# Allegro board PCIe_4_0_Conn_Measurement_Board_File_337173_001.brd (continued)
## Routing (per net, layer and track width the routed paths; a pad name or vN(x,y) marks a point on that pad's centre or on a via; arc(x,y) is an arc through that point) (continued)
GND3: length 97.5
  TOP w0.259: R48.1 v1(73.66,13.82) ; R49.1 v1(74.93,13.82) ; R47.1 v1(71.12,12.55) ; R45.1 v1(59.69,13.69) ; R46.1 v1(70.1,12.55) ; R44.1 v1(55.25,13.94)
  TOP w0.508: v1(56.54,6.01) 56.44,6.01 56.05,5.62 P1.B13 ; P1.A18 61.05,5.61 61.44,6.01 v1(61.54,6.01) ; 65.39,6.01 63.72,6.01 ; 65.39,6.01 v1(65.54,6.01) ; 65.39,6.01 65.05,5.66 P1.B22 ; 63.72,6.01 v1(63.54,6.01) ; 63.72,6.01 64.05,5.68 P1.B21 ; v1(44.54,6.01) 44.45,6.01 44.05,5.6 P1.A3 ; v1(49.54,6.01) 49.64,6.01 50.05,5.6 P1.A9 ; 67.72,6.01 68.05,5.68 P1.B25 ; 67.72,6.01 v1(67.54,6.01) ; 67.72,6.01 69.34,6.01 ; v1(45.54,6.01) 45.44,6.01 45.05,5.61 P1.A4 ; P1.B16 59.05,5.6 58.64,6.01 v1(58.55,6.01) ; P1.A10 51.05,5.59 51.46,6.01 v1(51.55,6.01) ; P1.B29 72.05,5.59 71.63,6.01 v1(71.55,6.01) ; P1.A1 42.05,5.6 42.45,6.01 v1(42.55,6.01) ; P1.B26 69.05,5.71 69.34,6.01 ; v1(69.55,6.01) 69.34,6.01 ; v1(43.55,6.01) 43.45,6.01 43.05,5.61 P1.A2 ; v1(74.54,6.01) 74.63,6.01 75.05,5.59 P1.B32 ; v1(47.55,6.01) 47.64,6.01 48.05,5.6 P1.B7
  BOTTOM w0.259: R50.2 v1(61.34,13.69) ; R51.2 v1(69.22,12.04) ; v1(71.83,12.04) 71.75,11.96 R53.2 ; R54.2 v1(72.77,12.04) ; R52.2 v1(68.2,12.04) ; R55.2 v1(75.95,13.82)
  BOTTOM w0.508: P1.A1 42.05,5.63 42.43,6.01 v1(42.55,6.01) ; v1(61.54,6.01) 61.46,6.01 61.05,5.6 P1.A18 ; v1(69.55,6.01) 69.84,6.01 ; 69.84,6.01 71.26,6.01 ; 69.84,6.01 70.05,5.8 P1.A27 ; 71.26,6.01 71.05,5.79 P1.A28 ; 71.26,6.01 v1(71.55,6.01) ; P1.A24 67.05,5.8 67.26,6.01 ; v1(67.54,6.01) 67.26,6.01 ; 67.26,6.01 65.82,6.01 ; v1(49.54,6.01) 49.83,6.01 ; 49.83,6.01 50.05,5.79 P1.A9 ; 49.83,6.01 51.27,6.01 ; P1.A12 55.05,5.61 55.45,6.01 v1(55.55,6.01) ; v1(44.54,6.01) 44.43,6.01 44.05,5.63 P1.A3 ; 65.82,6.01 v1(65.54,6.01) ; 65.82,6.01 66.05,5.78 P1.A23 ; v1(58.55,6.01) 58.46,6.01 58.05,5.6 P1.A15 ; v1(51.55,6.01) 51.27,6.01 ; 51.27,6.01 51.05,5.78 P1.A10 ; P1.A31 74.05,5.59 74.46,6.01 v1(74.54,6.01) ; v1(63.54,6.01) 63.46,6.01 63.05,5.59 P1.A20 ; v1(43.55,6.01) 43.43,6.01 43.05,5.63 P1.A2 ; P1.A4 45.05,5.63 45.43,6.01 v1(45.54,6.01)
  vias: v2(23.81,15.1) v2(23.81,14.19) v2(24.27,15.31) v2(24.27,13.98) v2(24.73,15.1) v2(24.73,14.19) v2(32.67,32.55) v2(32.88,33.01) v2(32.88,32.1) v2(33.8,33.01) v2(33.8,32.1) v2(34,32.55) v2(43.53,41.69) v2(43.74,42.15) v2(43.74,41.23) v2(44.65,42.15) v2(44.65,41.23) v2(44.86,41.69) v2(54.99,43.95) v2(55.19,44.41) v2(55.19,43.5) v2(56.11,44.41) v2(56.11,43.5) v2(56.31,43.95) v2(63.31,31.59) v2(63.31,30.67) v2(63.77,31.79) v2(63.77,30.47) v2(64.22,31.59) v2(64.22,30.67) v2(74.76,46.19) v2(74.97,46.65) v2(74.97,45.74) v2(75.88,46.65) v2(75.88,45.74) v2(76.09,46.19) v2(83.36,36.34) v2(83.56,36.8) v2(83.56,35.88) v2(84.48,36.8) v2(84.48,35.88) v2(84.68,36.34) v2(93.23,22.84) v2(93.44,23.3) v2(93.44,22.38) v2(94.35,23.3) v2(94.35,22.38) v2(94.56,22.84) v2(95.11,32.48) v2(95.11,31.56) v2(95.57,32.68) v2(95.56,31.36) v2(96.03,32.48) v2(96.02,31.56) v2(103.48,15.11) v2(103.48,14.19) v2(103.93,15.31) v2(103.93,13.99) v2(104.39,15.11) v2(104.39,14.19)
CLKREQ-GF1: length 7.4
  TOP w0.198: P1.B12 54.95,3.73 54.95,10.2 arc(55.03,10.59) C35.1
CLKREQ-GF2: length 7.4
  TOP w0.198: P2.B12 308.95,3.73 308.95,10.2 arc(309.03,10.59) C29.1
FACE2FACE: length 16.5
  TOP w0.198: J112.1 J106.1
FACE2FACE_TH: length 16.5
  BOTTOM w0.198: 288.16,227.37 J118.1
LOAD: length 45.7
  TOP w0.198: R66.2 63.12,246.42 ; 63.12,246.42 R67.2 ; 63.12,246.42 J105.1
LOAD_TH_TH: length 45.7
  BOTTOM w0.198: R69.2 317.12,246.42 ; 317.12,246.42 R68.2 ; 317.12,246.42 J117.1
PRESENT1-GF1: length 7.7
  TOP w0.198: P1.B31 73.95,3.73 73.95,8.68 arc(74.21,9.95) C38.1
PRESENT1-GF2: length 7.7
  TOP w0.198: P2.B31 327.95,3.73 327.95,8.68 arc(328.21,9.95) C32.1
PRESENT-GF1: length 7.4
  TOP w0.198: P1.B17 60.05,10.05 arc(59.95,10.51) C36.1
PRESENT-GF2: length 7.4
  TOP w0.198: P2.B17 314.05,10.05 arc(313.95,10.51) C30.1
PRIMARY_THRU: length 91.5
  TOP w0.198: J111.1 71.81,265.47 arc(70.84,265.28) 70.03,264.73 69.54,264.24 arc(66.77,262.4) 63.51,261.75 60.88,261.75 arc(57.8,262.36) 55.19,264.1 54.7,264.59 arc(53.73,265.24) 52.57,265.47 51.46,265.47 arc(50.8,265.6) 50.25,265.97 49.16,267.06 arc(48.23,267.68) 47.15,267.89 43.37,267.89 arc(42.03,267.63) 40.9,266.87 40.62,266.59 arc(39.38,265.76) 37.91,265.47 J104.1
PRIMARY_THRU_TH: length 91.5
  BOTTOM w0.198: J123.1 325.81,265.47 arc(324.84,265.28) 324.03,264.73 323.54,264.24 arc(320.77,262.4) 317.51,261.75 314.88,261.75 arc(311.8,262.36) 309.19,264.1 308.7,264.59 arc(307.73,265.24) 306.57,265.47 305.46,265.47 arc(304.8,265.6) 304.25,265.97 303.16,267.06 arc(302.23,267.68) 301.15,267.89 297.37,267.89 arc(296.03,267.63) 294.9,266.87 294.62,266.59 arc(293.38,265.76) 291.91,265.47 J116.1
PWRBRK-GF1: length 7.6
  TOP w0.198: P1.B30 73.05,9.56 arc(73.21,10.36) C37.1
PWRBRK-GF2: length 7.6
  TOP w0.198: P2.B30 327.05,9.56 arc(327.21,10.36) C31.1
REFCLK-SMT_N: length 2.9
  TOP w0.198: J66.A13 69.05,359.14 69.07,359.16 R64.1
REFCLK-SMT_P: length 2.9
  TOP w0.198: J66.A14 69.06,358.14 69.07,358.14 R65.1
REFCLK-TH_N: length 5.1
  BOTTOM w0.198: J44.A13 318.77,359.33 arc(319.02,359.16) 319.31,359.11 arc(319.47,359.14) 319.6,359.23 arc(319.72,359.31) 319.86,359.33 323.5,359.33 arc(323.6,359.35) R62.1
REFCLK-TH_P: length 5.1
  BOTTOM w0.198: R63.1 arc(325.33,358.62) 324.93,358.7 321.58,358.7 arc(321.13,358.61) J44.A14
RSVD1-GF1: length 7.7
  BOTTOM w0.198: P1.A32 75.15,3.73 75.15,9.1 arc(75.35,10.15) C34.2
RSVD1-GF2: length 7.7
  BOTTOM w0.198: P2.A32 329.15,3.73 329.15,9.1 arc(329.35,10.15) C28.2
RSVD-GF1: length 7.5
  BOTTOM w0.198: P1.A19 62.15,3.74 62.15,6.54 arc(62.1,6.79) 61.97,7 61.9,7.06 arc(61.74,7.3) 61.68,7.58 61.68,10.07 arc(61.59,10.52) C33.2
RSVD-GF2: length 7.5
  BOTTOM w0.198: P2.A19 316.15,3.74 316.15,7.08 arc(316.06,7.54) 315.8,7.94 arc(315.65,8.16) 315.6,8.43 315.6,10.28 arc(315.53,10.62) C27.2
RX0-GF1_N: length 47
  BOTTOM w0.198: P1.A16 59.13,3.72 59.13,6.52 arc(59,7.2) 58.61,7.77 58.46,7.92 58.02,8.36 arc(57.86,8.54) 57.7,8.72 arc(57.56,8.89) 57.43,9.07 arc(56.8,10.02) 56.58,11.14 56.58,17.96 arc(55.96,21.07) 54.2,23.7 arc(53.02,24.49) 51.63,24.77 48.31,24.77 arc(45.4,25.97) 44.19,28.88 J100.1
RX0-GF1_P: length 47
  BOTTOM w0.198: P1.A17 60.05,8.43 arc(59.91,9.12) 59.52,9.71 59.5,9.72 arc(58.9,10.63) 58.69,11.7 58.69,13.55 arc(59.06,15.42) 60.11,17 60.15,17.04 61.87,18.76 arc(65.47,21.16) 69.71,22 71.98,22 arc(73.14,22.23) 74.12,22.89 arc(74.53,23.5) 74.68,24.23 74.68,26.41 arc(74.43,27.64) 73.74,28.68 72.1,30.31 arc(71.19,30.92) 70.13,31.13 J101.1
RX0-GF2_N: length 48.9
  BOTTOM w0.198: P2.A16 313.13,3.72 313.13,6.52 arc(313,7.2) 312.61,7.77 312.46,7.92 312.02,8.36 arc(311.86,8.54) 311.7,8.72 arc(311.56,8.89) 311.43,9.07 arc(310.8,10.02) 310.58,11.14 310.58,17.96 arc(309.96,21.07) 308.2,23.7 arc(307.02,24.49) 305.63,24.77 300.73,24.77 arc(299.47,25.02) 298.4,25.73 297.21,26.92 arc(296.6,28.38) 297.21,29.85 arc(297.94,30.94) 298.19,32.23 J82.1
RX0-GF2_P: length 49
  BOTTOM w0.198: J83.1 324.6,31.13 arc(326.94,30.66) 328.93,29.34 arc(329.27,28.83) 329.39,28.23 329.39,24.46 arc(329.22,23.64) 328.76,22.95 328.55,22.73 arc(327.74,22.19) 326.78,22 323.71,22 arc(319.47,21.16) 315.87,18.76 314.15,17.04 314.11,17 arc(313.06,15.42) 312.69,13.55 312.69,11.7 arc(312.9,10.63) 313.5,9.72 313.52,9.71 arc(313.91,9.12) 314.05,8.43 P2.A17
RX0-SMT_N: length 48
  TOP w0.198: J56.1 89.18,381.58 89.18,381.59 88.49,381.59 arc(86.64,381.96) 85.06,383.01 arc(81.46,384.5) 77.85,383.01 75.27,380.43 arc(73.82,378.25) 73.3,375.68 73.3,360.91 arc(72.9,358.86) 71.73,357.12 arc(70.64,356.39) 69.35,356.14 J66.A16
RX0-SMT_P: length 48
  TOP w0.198: J66.A17 72.22,355.14 arc(75.96,355.88) 79.13,358 arc(80.13,359.39) 80.61,361.04 arc(80.88,362.4) 81.65,363.56 87.11,369.01 arc(91.03,370.64) 94.94,369.01 96.68,367.28 arc(97.69,366.6) 98.88,366.37 J86.1
RX0-TH_N: length 47.6
  BOTTOM w0.198: J44.A16 320.11,356.35 arc(319.89,356.4) 319.7,356.53 arc(319.61,356.75) 319.7,356.97 319.77,357.05 arc(320.66,357.41) 321.54,357.05 arc(321.86,356.83) 322.24,356.76 325.69,356.76 arc(327.22,357.06) 328.51,357.92 arc(329.07,358.91) 329.26,360.03 329.26,374.98 arc(329.69,377.14) 330.91,378.97 arc(333.83,380.92) 337.26,381.6 345.14,381.6 J20.1
RX0-TH_P: length 47.6
  BOTTOM w0.198: J67.1 346.26,366.37 arc(343.5,365.82) 341.17,364.26 arc(339.71,362.07) 339.19,359.49 arc(338.91,358.05) 338.1,356.84 337.92,356.67 arc(336.32,355.6) 334.43,355.22 321.68,355.22 arc(321.51,355.25) 321.37,355.35 arc(321.25,355.43) 321.1,355.46 320.55,355.46 arc(320.23,355.52) 319.96,355.7 arc(319.53,355.88) 319.09,355.7 J44.A17
RX1-GF1_N: length 47
  BOTTOM w0.198: P1.A21 64.13,3.72 64.13,6.44 arc(64.06,6.8) 63.86,7.11 arc(63.53,7.6) 63.41,8.19 63.41,11.45 arc(63.82,13.49) 64.97,15.21 65.09,15.33 arc(67.18,16.73) 69.65,17.22 75.8,17.22 arc(78.42,17.74) 80.64,19.23 arc(81.9,21.11) 82.35,23.34 82.35,27.37 82.35,27.86 arc(82.59,29.07) 83.28,30.1 arc(83.83,30.93) 84.02,31.9 J102.1
RX1-GF1_P: length 47
  BOTTOM w0.198: J103.1 93.89,17.9 arc(93.4,15.39) 91.97,13.26 arc(89.98,11.92) 87.62,11.46 85.6,11.46 85.6,11.45 arc(82.81,12.01) 80.44,13.59 arc(78.94,14.59) 77.17,14.94 71.41,14.94 arc(69.33,14.53) 67.57,13.35 66.07,11.85 arc(65.24,10.46) 64.95,8.87 64.95,3.73 P1.A22
RX1-GF2_N: length 49
  BOTTOM w0.198: J84.1 338.02,30.32 arc(337.88,29.62) 337.49,29.03 336.85,28.39 arc(336.15,27.93) 335.33,27.76 arc(334.04,27.23) 333.5,25.93 333.5,23.51 arc(333.77,22.18) 334.52,21.06 arc(334.88,20.18) 334.52,19.3 333.56,18.35 arc(331.77,17.51) 329.8,17.22 323.65,17.22 arc(321.18,16.73) 319.09,15.33 318.97,15.21 arc(317.82,13.49) 317.41,11.45 317.41,8.19 arc(317.53,7.6) 317.86,7.11 arc(318.06,6.8) 318.14,6.44 318.14,3.72 P2.A21
RX1-GF2_P: length 49
  BOTTOM w0.198: P2.A22 318.95,3.73 318.95,8.87 arc(319.24,10.46) 320.07,11.85 321.04,12.82 321.57,13.35 arc(323.33,14.53) 325.41,14.94 331.91,14.94 arc(333.1,15.18) 334.11,15.86 arc(334.18,15.92) 334.24,15.98 334.29,16.03 arc(335.57,16.56) 336.85,16.03 340.18,12.7 arc(341.47,11.84) 343,11.54 arc(344.95,11.92) 346.61,13.03 arc(347.56,14.45) 347.89,16.13 J85.1
RX1-SMT_N: length 48
  TOP w0.198: J87.1 96.64,346.42 arc(94.84,345.67) 94.1,343.88 94.1,343.43 arc(93.83,342.11) 93.08,340.99 92.86,340.77 arc(92.61,340.6) 92.31,340.54 86.12,340.54 arc(85.03,340.76) 84.1,341.38 arc(83.61,342.11) 83.44,342.98 83.44,344.7 arc(83.11,346.33) 82.19,347.71 77.9,352.01 arc(74.86,353.26) 71.83,352.01 71.5,351.67 arc(70.9,351.28) 70.21,351.14 J66.A21
RX1-SMT_P: length 48
  TOP w0.198: J88.1 80.18,327.72 arc(79.03,327.95) 78.05,328.6 arc(77.58,329.3) 77.42,330.13 77.42,331.11 arc(77.55,331.77) 77.93,332.33 arc(78.73,333.53) 79.01,334.95 arc(78.69,336.57) 77.77,337.94 77.57,338.14 arc(77.31,338.5) 77.01,338.84 76.45,339.39 arc(75.36,341.03) 74.98,342.95 74.98,343.39 arc(74.49,345.88) 73.08,347.99 72.73,348.34 arc(70.74,349.67) 68.39,350.14 J66.A22
RX1-TH_N: length 47.6
  BOTTOM w0.198: J44.A21 318.74,351.31 arc(318.79,351.06) 318.94,350.85 arc(319.14,350.7) 319.39,350.64 arc(319.73,350.71) 320.01,350.9 320.29,351.18 arc(320.7,351.45) 321.18,351.55 326.13,351.55 arc(326.79,351.68) 327.36,352.06 arc(329.37,352.89) 331.38,352.06 336.22,347.22 arc(336.97,346.22) 337.4,345.05 337.4,344.71 arc(337.75,342.94) 338.76,341.43 arc(339.66,340.83) 340.72,340.61 344.04,340.61 arc(345.08,340.82) 345.96,341.41 350.14,345.6 arc(351.05,346.2) 352.12,346.42 J68.1
RX1-TH_P: length 47.6
  BOTTOM w0.198: J69.1 337.64,327.72 arc(335.83,328.08) 334.29,329.11 arc(332.47,331.83) 331.83,335.04 331.83,338.2 arc(331.83,338.35) 331.83,338.51 331.83,338.84 arc(331.82,339.1) 331.81,339.36 331.81,341.05 arc(331.2,344.11) 329.47,346.7 328.84,347.33 arc(326.58,348.84) 323.9,349.38 320.17,349.38 arc(319.93,349.47) 319.84,349.71 319.84,349.77 arc(319.87,349.96) 319.98,350.12 320.01,350.15 arc(320.24,350.3) 320.5,350.35 J44.A22
RX2-GF1_N: length 7.3
  BOTTOM w0.259: P1.A25 68.11,3.7 68.11,10.69 arc(68.13,10.81) R52.1
RX2-GF1_P: length 7.4
  BOTTOM w0.259: P1.A26 68.96,3.72 68.96,10.3 arc(69.03,10.63) R51.1
RX2-GF2_N: length 7.3
  BOTTOM w0.259: P2.A25 322.11,3.7 322.11,10.69 arc(322.13,10.81) R40.1
RX2-GF2_P: length 7.4
  BOTTOM w0.259: P2.A26 322.96,3.72 322.96,10.3 arc(323.03,10.63) R39.1
RX2-SMT_N: length 2.9
  TOP w0.259: R59.1 69.01,347.09 68.96,347.14 J66.A25
RX2-SMT_P: length 2.9
  TOP w0.259: R58.1 69.01,346.08 68.95,346.14 J66.A26
RX2-TH_N: length 5.1
  BOTTOM w0.259: J44.A25 318.74,347.14 arc(318.76,346.96) 318.81,346.79 318.88,346.72 arc(319.29,346.55) 319.7,346.72 320.18,347.21 arc(320.43,347.37) 320.73,347.43 322.71,347.43 arc(322.82,347.41) R28.1
RX2-TH_P: length 5.1
  BOTTOM w0.259: J44.A26 arc(321.11,346.6) 321.54,346.68 324.81,346.68 arc(325.27,346.59) R27.1
RX3-GF1_N: length 7.4
  BOTTOM w0.259: P1.A29 72.16,3.75 72.16,9.93 arc(72.06,10.46) R53.1
RX3-GF1_P: length 7.4
  BOTTOM w0.259: P1.A30 73.05,10.24 arc(72.98,10.6) R54.1
RX3-GF2_N: length 7.4
  BOTTOM w0.259: P2.A29 326.16,3.75 326.16,9.93 arc(326.06,10.46) R41.1
RX3-GF2_P: length 7.4
  BOTTOM w0.259: P2.A30 327.05,10.24 arc(326.98,10.6) R42.1
RX3-SMT_N: length 2.9
  TOP w0.259: J66.A29 68.99,343.14 69.01,343.15 R60.1
RX3-SMT_P: length 2.9
  TOP w0.259: R61.1 69.01,342.14 69.01,342.14 J66.A30
RX3-TH_N: length 5.1
  BOTTOM w0.259: J44.A29 318.74,343.27 arc(318.77,343.03) 318.86,342.8 318.87,342.78 arc(319.33,342.59) 319.78,342.78 320.21,343.2 arc(320.63,343.49) 321.12,343.59 322.52,343.59 arc(322.75,343.54) R29.1
RX3-TH_P: length 5.1
  BOTTOM w0.259: J44.A30 arc(321.14,342.62) 321.6,342.71 324.9,342.71 arc(325.31,342.63) R30.1
SECONDARY1: length 95.5
  TOP w0.198: J108.1 27.95,188.96 arc(29.75,188.22) 30.49,186.42 30.49,185.9 arc(30.82,184.27) 31.74,182.89 32.38,182.25 arc(35.9,179.9) 40.05,179.07 53.84,179.07 arc(58.84,181.14) 60.91,186.14 60.91,187.59 arc(61.31,188.56) 62.28,188.96 J113.1
SECONDARY1_TH: length 95.5
  BOTTOM w0.198: J120.1 281.95,188.96 arc(283.75,188.22) 284.49,186.42 284.49,185.9 arc(284.82,184.27) 285.74,182.89 286.39,182.25 arc(289.9,179.9) 294.05,179.07 307.84,179.07 arc(312.84,181.14) 314.91,186.14 314.91,187.59 arc(315.31,188.56) 316.28,188.96 J125.1
SECONDARY2: length 103.7
  TOP w0.198: J114.1 77.27,161.17 arc(75.47,161.91) 74.73,163.71 74.73,165.96 arc(72.99,170.15) 68.81,171.88 50.35,171.88 arc(48.56,171.53) 47.04,170.51 arc(46.21,169.27) 45.92,167.81 45.92,163.52 arc(45.73,162.56) 45.19,161.75 arc(44.38,161.21) 43.43,161.02 J109.1
SECONDARY2_TH: length 103.7
  BOTTOM w0.198: J121.1 297.43,161.02 arc(298.38,161.21) 299.19,161.75 arc(299.73,162.56) 299.92,163.52 299.92,167.81 arc(300.21,169.27) 301.04,170.51 arc(302.56,171.53) 304.35,171.88 322.81,171.88 arc(326.99,170.15) 328.73,165.96 328.73,163.71 arc(329.47,161.91) 331.27,161.17 J126.1
SECONDARY3: length 143
  TOP w0.198: J115.1 101.73,144.82 101.73,144.82 85.38,144.82 arc(84.4,144.62) 83.58,144.07 83.47,143.97 arc(82.92,143.14) 82.73,142.17 82.73,136.88 arc(82.73,136.71) 82.72,136.55 82.72,132.59 arc(82.53,131.62) 81.98,130.8 81.9,130.72 arc(81.07,130.17) 80.1,129.97 68.4,129.97 arc(67.49,130.15) 66.71,130.67 arc(66.2,131.44) 66.01,132.36 66.01,144.96 arc(65.84,145.83) 65.35,146.56 arc(61.6,149.07) 57.17,149.95 55.88,149.95 arc(52.02,149.18) 48.74,146.99 48.51,146.76 arc(47.27,144.9) 46.83,142.7 46.83,133.9 arc(46.81,133.64) 46.73,133.4 46.63,133.15 arc(46.62,133.11) 46.61,133.06 46.61,133.04 46.34,132.77 arc(44.71,131.68) 42.8,131.3 33.16,131.3 arc(31.12,131.7) 29.4,132.86 arc(29.13,133.26) 29.03,133.74 29.03,142.28 arc(28.29,144.07) 26.49,144.82 J110.1
SECONDARY3_TH: length 143
  BOTTOM w0.198: J127.1 355.73,144.82 355.73,144.82 339.38,144.82 arc(338.4,144.62) 337.58,144.07 337.47,143.97 arc(336.92,143.14) 336.73,142.17 336.73,136.88 arc(336.73,136.71) 336.72,136.55 336.72,132.59 arc(336.53,131.62) 335.98,130.8 335.9,130.72 arc(335.07,130.17) 334.1,129.97 322.4,129.97 arc(321.49,130.15) 320.71,130.67 arc(320.2,131.44) 320.01,132.36 320.01,144.96 arc(319.84,145.83) 319.35,146.56 arc(315.6,149.07) 311.17,149.95 309.88,149.95 arc(306.02,149.18) 302.74,146.99 302.51,146.76 arc(301.27,144.9) 300.83,142.7 300.83,133.9 arc(300.81,133.64) 300.73,133.4 300.63,133.15 arc(300.62,133.11) 300.61,133.06 300.61,133.04 300.34,132.77 arc(298.71,131.68) 296.8,131.3 287.16,131.3 arc(285.12,131.7) 283.4,132.86 arc(283.13,133.26) 283.03,133.74 283.03,142.28 arc(282.29,144.07) 280.49,144.82 J122.1
TX0-GF1_N: length 47
  TOP w0.198: J94.1 39.21,14.65 arc(40.3,14.43) 41.22,13.81 arc(41.52,13.22) 41.94,12.7 arc(43.52,11.64) 45.39,11.27 arc(47.44,11.68) 49.17,12.84 51.84,15.51 arc(52.56,15.99) 53.41,16.15 54.27,16.15 arc(55.23,15.96) 56.05,15.42 arc(56.52,14.7) 56.69,13.85 56.69,7.37 arc(56.73,7.17) 56.85,6.99 arc(57.06,6.67) 57.14,6.3 57.14,3.72 P1.B14
TX0-GF1_P: length 47
  TOP w0.198: J95.1 33.34,28.45 arc(33.76,26.35) 34.95,24.56 arc(40.41,20.91) 46.85,19.63 53.53,19.63 arc(54.74,19.39) 55.77,18.71 57.76,16.71 arc(58.19,16.07) 58.34,15.3 58.34,7.33 arc(58.29,7.08) 58.15,6.87 arc(58.01,6.66) 57.96,6.41 57.96,3.72 P1.B15
TX0-GF2_N: length 48.9
  TOP w0.198: P2.B14 311.14,3.72 311.14,6.3 arc(311.06,6.67) 310.85,6.99 arc(310.73,7.17) 310.69,7.37 310.69,13.85 arc(310.52,14.7) 310.05,15.42 arc(309.23,15.96) 308.27,16.15 307.41,16.15 arc(306.56,15.99) 305.84,15.51 303.17,12.84 arc(301.44,11.68) 299.39,11.27 arc(297.52,11.64) 295.94,12.7 arc(295.88,12.75) 295.83,12.81 295.81,12.83 arc(295.38,13.48) 295.22,14.25 arc(294.62,15.7) 293.17,16.31 292.25,16.31 arc(291.69,16.19) 291.21,15.88 290.42,15.09 arc(289.93,14.76) 289.36,14.65 J76.1
TX0-GF2_P: length 49
  TOP w0.198: J77.1 287.34,26.12 arc(287.86,23.52) 289.33,21.31 arc(291.19,20.07) 293.38,19.63 306.11,19.63 arc(308.63,19.13) 310.77,17.7 311.76,16.71 arc(312.19,16.07) 312.34,15.3 312.34,7.33 arc(312.29,7.08) 312.15,6.87 arc(312.01,6.66) 311.96,6.41 311.96,3.72 P2.B15
TX0-SMT_N: length 48
  TOP w0.198: J66.B14 57.91,358.14 arc(56.36,358.45) 55.04,359.33 arc(54.58,360.01) 54.42,360.81 54.42,366.29 arc(54.13,367.74) 53.31,368.96 arc(52.33,369.68) 51.17,370.07 arc(50.4,370.22) 49.74,370.66 48.74,371.66 arc(47.9,373.69) 48.74,375.72 49.4,376.38 arc(50.55,377.14) 51.89,377.41 arc(53.79,377.79) 55.4,378.86 55.88,379.35 arc(56.14,380.72) 55.62,382.02 arc(53.94,383.14) 51.95,383.54 49.53,383.54 arc(48.63,383.91) 48.26,384.81 J60.1
TX0-SMT_P: length 48
  TOP w0.198: J66.B15 56.69,357.14 arc(56.17,357.03) 55.73,356.74 arc(55.3,356.45) 54.8,356.35 50.95,356.35 arc(49.11,356.72) 47.54,357.77 47.47,357.84 46.89,358.42 arc(46.57,358.8) 46.34,359.24 46.18,359.62 arc(46.1,359.9) 46.07,360.18 46.07,362.07 arc(46.06,362.49) 46.04,362.91 arc(45.6,365.09) 44.37,366.93 40.97,370.33 arc(40.22,371.46) 39.95,372.78 39.95,377 arc(40.01,377.27) 40.15,377.49 arc(40.31,377.79) 40.36,378.12 40.36,378.52 arc(40.18,379.45) 39.65,380.24 arc(38.31,381.14) 36.73,381.45 arc(35.31,381.17) 34.11,380.37 33.97,380.23 arc(33.2,379.71) 32.28,379.53 J89.1
TX0-TH_N: length 47.6
  BOTTOM w0.198: J70.1 302.26,384.4 arc(302.4,383.7) 302.8,383.09 302.81,383.09 arc(303.29,382.89) 303.81,382.82 305.27,382.82 arc(306.78,382.52) 308.05,381.66 arc(308.7,380.11) 308.05,378.55 arc(307,377.81) 305.76,377.46 arc(305.22,377.35) 304.76,377.04 303.8,376.09 302.68,374.97 arc(301.85,372.96) 302.68,370.95 arc(303.41,370.43) 304.27,370.18 arc(305.02,370.03) 305.66,369.6 306.81,368.45 arc(308,366.67) 308.42,364.57 308.42,362.74 arc(308.67,361.37) 309.37,360.18 arc(310.32,359.55) 311.42,359.33 314.38,359.33 arc(314.72,359.27) 315,359.07 315.11,358.97 arc(315.17,358.89) 315.19,358.81 315.19,358.67 arc(315.14,358.4) 314.99,358.17 arc(314.71,358.05) 314.43,358.17 J44.B14
TX0-TH_P: length 47.6
  BOTTOM w0.198: J71.1 290.11,379.53 arc(292.21,379.11) 293.98,377.92 arc(295.13,376.2) 295.53,374.18 arc(295.33,373.14) 294.74,372.26 arc(294.05,370.6) 294.74,368.94 299.46,364.21 arc(299.91,363.55) 300.07,362.76 arc(300.5,361.4) 301.34,360.25 301.8,359.79 302.34,359.25 arc(304.46,357.84) 306.96,357.34 314.93,357.34 arc(315.03,357.36) 315.11,357.42 315.33,357.63 arc(315.73,357.8) 316.13,357.63 arc(316.21,357.5) J44.B15
TX1-GF1_N: length 47
  TOP w0.198: P1.B19 62.12,3.7 62.12,19.43 arc(61.96,20.23) 61.51,20.9 arc(60.56,21.53) 59.45,21.76 57.53,21.76 arc(55.85,22.09) 54.43,23.04 arc(53.53,24.39) 53.21,25.98 53.21,34.19 arc(53.55,35.9) 54.52,37.34 arc(55.36,38.6) 55.65,40.07 J96.1
TX1-GF1_P: length 47
  TOP w0.198: P1.B20 62.97,3.71 62.97,6.38 arc(63.04,6.83) 63.26,7.23 arc(63.6,7.73) 63.72,8.32 63.72,12.18 arc(63.74,12.99) 63.83,13.8 arc(64.7,18.2) 67.2,21.93 74.81,29.55 arc(75.27,30.23) 75.43,31.03 J97.1
TX1-GF2_N: length 49
  TOP w0.198: P2.B19 316.12,3.7 316.12,19.43 arc(315.96,20.23) 315.51,20.9 arc(314.56,21.53) 313.45,21.76 310.51,21.76 arc(308.27,22.2) 306.37,23.47 arc(305.92,24.14) 305.77,24.94 305.77,30.7 arc(306.48,34.29) 308.52,37.34 arc(309.36,38.6) 309.65,40.07 J78.1
TX1-GF2_P: length 49
  TOP w0.198: J79.1 329.43,41.68 arc(329.31,41.11) 328.99,40.62 327.2,38.84 arc(326.81,38.25) 326.67,37.55 326.67,37.29 arc(326.95,35.86) 327.77,34.64 328.66,33.74 arc(329.36,32.7) 329.61,31.47 arc(329.4,30.43) 328.81,29.55 321.2,21.93 arc(318.7,18.2) 317.83,13.8 arc(317.74,12.99) 317.72,12.18 317.72,8.32 arc(317.6,7.73) 317.26,7.23 arc(317.04,6.83) 316.97,6.38 316.97,3.71 P2.B20
TX1-SMT_N: length 48
  TOP w0.198: J66.B19 48.87,353.14 arc(47.78,352.92) 46.84,352.3 arc(45.93,351.82) 44.91,351.65 44.57,351.65 arc(42.48,352.07) 40.7,353.25 arc(40.29,353.92) 40.15,354.69 arc(40.34,355.83) 40.97,356.79 41.5,357.32 arc(41.6,357.44) 41.71,357.55 arc(42.17,358.38) 42.44,359.29 42.44,359.66 arc(42.44,359.85) 42.42,360.05 arc(42.11,361.63) 41.21,362.98 39.01,365.18 arc(37.41,366.25) 35.52,366.62 arc(33.7,366.26) 32.16,365.23 29.62,362.69 arc(28.73,362.1) 27.69,361.89 J90.1
TX1-SMT_P: length 48
  TOP w0.198: J66.B20 55.43,352.14 arc(53.26,351.7) 51.42,350.47 arc(48.77,348.9) 45.74,348.35 42.29,348.35 arc(40.94,348.62) 39.79,349.39 38.79,350.39 arc(37.46,351.28) 35.9,351.59 30.8,351.59 arc(30.13,351.45) 29.56,351.07 26.98,348.5 arc(25.56,347.54) 23.88,347.21 J91.1
TX1-TH_N: length 47.6
  BOTTOM w0.198: J72.1 285.01,361.89 arc(285.73,362.03) 286.34,362.44 286.69,362.79 arc(289.85,364.1) 293.01,362.79 294.78,361.03 arc(295.58,359.82) 295.87,358.39 295.87,357.96 arc(295.66,357.46) 295.33,357.02 arc(294.49,355) 295.33,352.98 296.14,352.17 arc(297.82,351.38) 299.62,351.85 arc(299.82,352.04) 300.03,352.22 arc(301.5,353.04) 303.16,353.32 314.52,353.32 arc(314.83,353.26) 315.09,353.09 315.28,352.89 arc(315.47,352.76) 315.69,352.72 arc(315.84,352.75) 315.96,352.83 316.07,352.94 arc(316.2,353.13) J44.B19
TX1-TH_P: length 47.6
  BOTTOM w0.198: J73.1 276.76,347.21 arc(278.43,346.88) 279.85,345.93 arc(280.95,345.19) 282.26,344.93 283.23,344.93 arc(286.41,345.57) 289.12,347.37 290.41,348.67 arc(291.95,349.3) 293.5,348.67 arc(293.84,348.44) 294.25,348.35 299.74,348.35 arc(302.51,348.81) 304.99,350.12 arc(306.37,351.05) 308.01,351.37 314.49,351.37 arc(314.75,351.42) 314.97,351.57 315.11,351.71 arc(315.2,351.92) 315.11,352.13 315.1,352.15 arc(314.87,352.3) 314.6,352.35 J44.B20
TX2-GF1_N: length 47
  TOP w0.198: J98.1 92.98,32.02 arc(84.04,30.24) 76.46,25.18 67.88,16.6 arc(65.95,13.7) 65.27,10.29 arc(65.26,10.17) 65.26,10.06 65.26,8.98 arc(65.29,8.69) 65.37,8.42 arc(65.51,8.15) 65.7,7.92 arc(66.03,7.43) 66.14,6.86 66.14,3.73 P1.B23
TX2-GF1_P: length 47
  TOP w0.198: J99.1 92.34,14.65 arc(91.52,14.48) 90.83,14.02 90.35,13.54 arc(90.12,13.39) 89.86,13.34 84.04,13.34 arc(83.65,13.41) 83.32,13.63 arc(82.2,14.38) 80.87,14.65 71.15,14.65 arc(69.62,14.34) 68.33,13.47 67.99,13.14 arc(67.64,12.61) 67.51,11.99 67.51,7.92 arc(67.42,7.47) 67.16,7.08 arc(66.99,6.82) 66.93,6.51 66.93,3.75 P1.B24
TX2-GF2_N: length 49
  TOP w0.198: P2.B23 320.14,3.73 320.14,6.86 arc(320.03,7.43) 319.7,7.92 arc(319.51,8.15) 319.37,8.42 arc(319.29,8.69) 319.26,8.98 319.26,10.06 arc(319.26,10.17) 319.27,10.29 arc(319.95,13.7) 321.88,16.6 327.82,22.54 arc(328.77,23.17) 329.89,23.39 335.56,23.39 arc(337.14,24.05) 337.79,25.63 arc(338.13,27.29) 339.07,28.71 341.33,30.97 arc(342.49,31.74) 343.86,32.02 349.57,32.02
TX2-GF2_P: length 49
  TOP w0.198: J81.1 353.24,14.65 arc(352.12,14.87) 351.17,15.5 350.85,15.82 arc(349.98,16.41) 348.95,16.61 arc(347.54,16.33) 346.34,15.53 344.35,13.54 arc(342.79,12.5) 340.95,12.13 arc(338.98,12.52) 337.32,13.63 arc(336.2,14.38) 334.87,14.65 325.15,14.65 arc(323.62,14.34) 322.33,13.47 321.99,13.14 arc(321.64,12.61) 321.51,11.99 321.51,7.92 arc(321.42,7.47) 321.16,7.08 arc(320.99,6.82) 320.93,6.51 320.93,3.75 P2.B24
TX2-SMT_N: length 48
  TOP w0.198: J66.B23 55.49,349.14 arc(53.19,348.68) 51.24,347.38 48.81,344.95 47.74,343.88 arc(46.35,342.95) 44.7,342.62 44.04,342.62 arc(42.38,342.29) 40.98,341.35 40.98,341.35 arc(39.83,339.63) 39.42,337.59 39.42,335.47 arc(39.05,333.58) 37.98,331.98 37.67,331.68 arc(34.36,329.46) 30.46,328.69 J92.1
TX2-SMT_P: length 48
  TOP w0.198: J93.1 38.15,321.86 arc(38.45,323.37) 39.3,324.65 40.64,325.98 arc(42.91,326.92) 45.19,325.98 arc(46.14,325.34) 47.27,325.12 arc(48.42,325.35) 49.39,326 49.63,326.24 arc(50.99,328.26) 51.46,330.65 51.46,342.08 arc(51.78,343.86) 52.7,345.41 54.43,347.13 arc(55.54,347.88) 56.85,348.14 J66.B24
TX2-TH_N: length 47.6
  BOTTOM w0.198: J74.1 278.44,331.25 290.73,331.25 arc(293.21,331.74) 295.31,333.14 arc(296.62,335.1) 297.08,337.41 arc(297.6,340.02) 299.07,342.23 302.54,345.7 arc(306.58,348.39) 311.33,349.34 314.33,349.34 arc(314.63,349.28) 314.88,349.11 315.06,348.93 arc(315.27,348.79) 315.52,348.74 315.74,348.74 arc(315.9,348.78) 316.04,348.87 arc(316.19,349.09) J44.B23
TX2-TH_P: length 47.6
  BOTTOM w0.198: J75.1 292.15,324.34 arc(292.45,325.85) 293.3,327.12 arc(294.44,327.89) 295.8,328.16 296.31,328.16 arc(299.14,328.72) 301.54,330.32 301.74,330.52 arc(304.49,334.64) 305.46,339.5 305.46,342.3 arc(305.96,344.28) 307.12,345.96 arc(308.64,346.98) 310.44,347.33 314.59,347.33 arc(314.96,347.4) 315.26,347.61 arc(315.38,347.9) 315.26,348.18 315.23,348.22 arc(315.08,348.32) 314.91,348.35 J44.B24
TX3-GF1_N: length 7.9
  TOP w0.259: P1.B27 70.15,3.74 70.15,11.37 R46.2
TX3-GF1_P: length 7.9
  TOP w0.259: P1.B28 70.97,3.71 70.97,11.05 arc(71.01,11.25) R47.2
TX3-GF2_N: length 7.9
  TOP w0.259: R34.2 324.15,11.37 324.15,3.74 P2.B27
TX3-GF2_P: length 7.9
  TOP w0.259: P2.B28 324.97,3.71 324.97,11.05 arc(325.01,11.25) R35.2
TX3-SMT_N: length 2.9
  TOP w0.259: J66.B27 58.06,345.14 58.01,345.19 R56.2
TX3-SMT_P: length 2.9
  TOP w0.259: R57.2 58.03,344.17 58.06,344.14 J66.B28
TX3-TH_N: length 5.1
  BOTTOM w0.259: J44.B27 315.88,344.99 arc(315.78,344.93) 315.67,344.9 315.29,344.9 arc(315.13,344.93) 315,345.02 314.74,345.27 arc(314.56,345.4) 314.35,345.44 R22.2
TX3-TH_P: length 5.1
  BOTTOM w0.259: R23.2 310.3,344.42 arc(310.5,344.46) 310.67,344.58 arc(310.86,344.71) 311.1,344.75 313.33,344.75 arc(313.81,344.66) 314.21,344.39 J44.B28
N295225: length 1.1
  TOP w0.198: C32.2 R37.2
N295261: length 1.1
  TOP w0.198: C31.2 R36.2
N295961: length 1.1
  BOTTOM w0.198: C27.1 R38.1
N295971: length 1.1
  TOP w0.198: C30.2 R33.2
N296497: length 1.1
  TOP w0.198: R32.2 C29.2
N311833: length 1.1
  TOP w0.198: C38.2 R49.2
N311853: length 1.1
  TOP w0.198: C37.2 R48.2
N312429: length 1.1
  BOTTOM w0.198: C33.1 R50.1
N312439: length 1.1
  TOP w0.198: C36.2 R45.2
N312937: length 1.2
  TOP w0.198: C35.2 R44.2
N2956010: length 1.1
  BOTTOM w0.198: C28.1 R43.1
N3120750: length 1.1
  BOTTOM w0.198: C34.1 R55.1

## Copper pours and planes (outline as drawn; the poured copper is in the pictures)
GND on BOTTOM (solid shape): outline of 320 points within 11.89,342.21 17.55,352.21
GND on BOTTOM (solid shape): outline of 320 points within 14.83,222.36 20.49,232.37
GND on BOTTOM (solid shape): outline of 320 points within 15.13,260.46 20.79,270.47
GND on BOTTOM (solid shape): outline of 320 points within 15.56,241.41 21.22,251.42
GND on BOTTOM (solid shape): outline of 320 points within 16.84,183.96 22.49,193.97
GND on BOTTOM (solid shape): outline of 320 points within 16.84,156.02 22.49,166.03
GND on BOTTOM (solid shape): outline of 320 points within 16.84,139.81 22.49,149.82
GND on BOTTOM (solid shape): outline of 320 points within 17.2,203.31 22.86,213.32
GND on BOTTOM (solid shape): outline of 320 points within 19.06,323.68 24.71,333.69
GND on BOTTOM (solid shape): outline of 320 points within 23.49,356.89 29.14,366.89
GND on BOTTOM (solid shape): outline of 320 points within 27.29,374.52 32.95,384.53
GND on BOTTOM (solid shape): outline of 320 points within 31.34,222.36 37,232.37
GND on BOTTOM (solid shape): outline of 320 points within 33.14,313.51 43.15,319.17
GND on BOTTOM (solid shape): outline of 320 points within 43.26,385.84 53.26,391.5
GND on BOTTOM (solid shape): outline of 320 points within 88.33,376.58 93.99,386.59
GND on BOTTOM (solid shape): outline of 321 points within 93.95,322.72 99.61,332.73
GND on BOTTOM (solid shape): outline of 322 points within 99.92,341.41 105.58,351.42
GND on BOTTOM (solid shape): outline of 320 points within 100.86,183.96 106.52,193.97
GND on BOTTOM (solid shape): outline of 320 points within 102.96,260.46 108.61,270.47
GND on BOTTOM (solid shape): outline of 322 points within 102.99,361.36 108.65,371.37
GND on BOTTOM (solid shape): outline of 320 points within 105.44,156.16 111.1,166.17
GND on BOTTOM (solid shape): outline of 320 points within 106.63,139.81 112.29,149.82
GND on L2: 3.05,79.38 1.34,80.08 0.64,81.79 0.64,412.24 1.34,413.95 3.05,414.65 123.95,414.65 125.51,414.09 126.33,412.65 126.33,81.38 125.51,79.94 123.95,79.38
GND on L3: 3.05,79.38 1.34,80.08 0.64,81.79 0.64,412.24 1.34,413.95 3.05,414.65 123.95,414.65 125.66,413.95 126.36,412.24 126.36,81.79 125.66,80.08 123.95,79.38
GND1 on TOP (solid shape): outline of 221 points within 287.14,313.51 297.15,319.17
GND1 on TOP (solid shape): outline of 222 points within 297.26,385.84 307.26,391.5
GND1 on TOP (solid shape): outline of 223 points within 353.92,341.41 359.58,351.42
GND1 on TOP (solid shape): outline of 223 points within 268.83,222.36 274.49,232.37
GND1 on TOP (solid shape): outline of 223 points within 269.09,342.21 274.75,352.21
GND1 on TOP (solid shape): outline of 223 points within 269.56,241.41 275.22,251.42
GND1 on TOP (solid shape): outline of 223 points within 270.84,183.96 276.49,193.97
GND1 on TOP (solid shape): outline of 223 points within 270.84,156.02 276.49,166.03
GND1 on TOP (solid shape): outline of 223 points within 270.84,139.81 276.49,149.82
GND1 on TOP (solid shape): outline of 223 points within 271.2,203.31 276.86,213.32
GND1 on TOP (solid shape): outline of 223 points within 275.6,326.22 281.25,336.23
GND1 on TOP (solid shape): outline of 223 points within 277.49,356.89 283.14,366.89
GND1 on TOP (solid shape): outline of 223 points within 281.29,374.52 286.95,384.53
GND1 on TOP (solid shape): outline of 223 points within 285.34,222.36 291,232.37
GND1 on TOP (solid shape): outline of 223 points within 342.33,376.58 347.99,386.59
GND1 on TOP (solid shape): outline of 223 points within 347.95,322.72 353.61,332.73
GND1 on TOP (solid shape): outline of 223 points within 354.86,183.96 360.52,193.97
GND1 on TOP (solid shape): outline of 223 points within 356.96,260.46 362.61,270.47
GND1 on TOP (solid shape): outline of 223 points within 356.99,361.36 362.65,371.37
GND1 on TOP (solid shape): outline of 223 points within 359.44,156.16 365.1,166.17
GND1 on TOP (solid shape): outline of 223 points within 360.63,139.81 366.29,149.82
GND1 on TOP (solid shape): outline of 224 points within 269.13,260.46 274.79,270.47
GND1 on BOTTOM (solid shape): outline of 275 points within 287.14,313.51 297.15,319.17
GND1 on BOTTOM (solid shape): outline of 276 points within 353.92,341.41 359.58,351.42
GND1 on BOTTOM (solid shape): outline of 276 points within 268.83,222.36 274.49,232.37
GND1 on BOTTOM (solid shape): outline of 276 points within 269.09,342.21 274.75,352.21
GND1 on BOTTOM (solid shape): outline of 276 points within 269.56,241.41 275.22,251.42
GND1 on BOTTOM (solid shape): outline of 276 points within 270.84,183.96 276.49,193.97
GND1 on BOTTOM (solid shape): outline of 276 points within 270.84,156.02 276.49,166.03
GND1 on BOTTOM (solid shape): outline of 276 points within 270.84,139.81 276.49,149.82
GND1 on BOTTOM (solid shape): outline of 276 points within 271.2,203.31 276.86,213.32
GND1 on BOTTOM (solid shape): outline of 276 points within 275.6,326.22 281.25,336.23
GND1 on BOTTOM (solid shape): outline of 276 points within 277.49,356.89 283.14,366.89
GND1 on BOTTOM (solid shape): outline of 276 points within 281.29,374.52 286.95,384.53
GND1 on BOTTOM (solid shape): outline of 276 points within 285.34,222.36 291,232.37
GND1 on BOTTOM (solid shape): outline of 276 points within 297.26,385.84 307.26,391.5
GND1 on BOTTOM (solid shape): outline of 276 points within 342.33,376.58 347.99,386.59
GND1 on BOTTOM (solid shape): outline of 276 points within 347.95,322.72 353.61,332.73
GND1 on BOTTOM (solid shape): outline of 276 points within 354.86,183.96 360.52,193.97
GND1 on BOTTOM (solid shape): outline of 276 points within 356.96,260.46 362.61,270.47
GND1 on BOTTOM (solid shape): outline of 276 points within 356.99,361.36 362.65,371.37
GND1 on BOTTOM (solid shape): outline of 276 points within 359.44,156.16 365.1,166.17
GND1 on BOTTOM (solid shape): outline of 276 points within 360.63,139.81 366.29,149.82
GND1 on BOTTOM (solid shape): outline of 277 points within 269.13,260.46 274.79,270.47
GND1 on L2: 257.05,79.38 255.34,80.08 254.64,81.79 254.64,412.24 255.34,413.95 257.05,414.65 377.95,414.65 379.51,414.09 380.33,412.65 380.33,81.38 379.51,79.94 377.95,79.38
GND1 on L3: 257.05,79.38 255.34,80.08 254.64,81.79 254.64,412.24 255.34,413.95 257.05,414.65 377.95,414.65 379.66,413.95 380.36,412.24 380.36,81.79 379.66,80.08 377.95,79.38
GND2 on TOP (solid shape): outline of 221 points within 293.19,38.86 303.2,44.52
GND2 on TOP (solid shape): outline of 221 points within 333.02,33.51 343.03,39.17
GND2 on TOP (solid shape): outline of 223 points within 314.94,26.13 320.6,36.13
GND2 on TOP (solid shape): outline of 222 points within 342.89,20.01 352.9,25.67
GND2 on TOP (solid shape): outline of 275 points within 282.33,29.72 292.34,35.38
GND2 on TOP (solid shape): outline of 275 points within 304.65,41.12 314.65,46.78
GND2 on TOP (solid shape): outline of 275 points within 324.42,43.36 334.43,49.02
GND2 on TOP (solid shape): outline of 275 points within 346.71,27.01 352.42,37.02
GND2 on TOP (solid shape): outline of 276 points within 275.44,9.64 281.1,19.65
GND2 on TOP (solid shape): outline of 276 points within 355.1,9.64 360.76,19.65
GND2 on BOTTOM (solid shape): outline of 221 points within 282.33,29.72 292.34,35.38
GND2 on BOTTOM (solid shape): outline of 221 points within 304.65,41.12 314.65,46.78
GND2 on BOTTOM (solid shape): outline of 221 points within 324.42,43.36 334.43,49.02
GND2 on BOTTOM (solid shape): outline of 222 points within 346.71,27.01 352.42,37.02
GND2 on BOTTOM (solid shape): outline of 223 points within 275.44,9.64 281.1,19.65
GND2 on BOTTOM (solid shape): outline of 223 points within 355.1,9.64 360.76,19.65
GND2 on BOTTOM (solid shape): outline of 275 points within 293.19,38.86 303.2,44.52
GND2 on BOTTOM (solid shape): outline of 275 points within 333.02,33.51 343.03,39.17
GND2 on BOTTOM (solid shape): outline of 276 points within 314.94,26.13 320.6,36.13
GND2 on BOTTOM (solid shape): outline of 277 points within 342.89,20.01 352.9,25.67
GND2 on L2: 295.78,5.61 295.77,6.01 295.71,6.75 296.09,7.24 295.53,8.59 294.18,9.14 257.05,9.14 255.34,9.85 254.64,11.56 254.64,73.15 255.34,74.86 257.05,75.56 377.95,75.56 379.66,74.86 380.36,73.15 380.36,11.56 379.66,9.85 377.95,9.14 331.01,9.14 329.79,8.57 329.46,7.27 329.4,5.62 329.41,5.61 308.78,5.61 308.75,5.64 308.7,7.16 308.75,8.17 307.69,8.9 306.46,8.49 306.44,7.24 306.41,5.76 306.44,5.61 306.44,5.61
GND2 on L3: 295.78,5.61 295.77,6.01 295.71,6.75 296.09,7.24 295.53,8.59 294.18,9.14 257.05,9.14 255.34,9.85 254.64,11.56 254.64,73.15 255.34,74.86 257.05,75.56 377.95,75.56 379.66,74.86 380.36,73.15 380.36,11.56 379.66,9.85 377.95,9.14 331.01,9.14 329.79,8.57 329.46,7.27 329.4,5.62 329.41,5.61 308.78,5.61 308.75,5.64 308.7,7.16 308.75,8.17 307.69,8.9 306.46,8.49 306.44,7.24 306.41,5.76 306.44,5.61
GND3 on TOP (solid shape): outline of 320 points within 39.19,38.86 49.2,44.52
GND3 on TOP (solid shape): outline of 320 points within 60.94,26.13 66.6,36.13
GND3 on TOP (solid shape): outline of 320 points within 79.02,33.51 89.03,39.17
GND3 on TOP (solid shape): outline of 320 points within 88.89,20.01 98.9,25.67
GND3 on BOTTOM (solid shape): outline of 320 points within 21.44,9.64 27.1,19.65
GND3 on BOTTOM (solid shape): outline of 320 points within 28.33,29.72 38.34,35.38
GND3 on BOTTOM (solid shape): outline of 322 points within 50.65,41.12 60.65,46.78
GND3 on BOTTOM (solid shape): outline of 320 points within 70.42,43.36 80.43,49.02
GND3 on BOTTOM (solid shape): outline of 320 points within 101.1,9.64 106.76,19.65
GND3 on BOTTOM (solid shape): outline of 321 points within 92.71,27.01 98.42,37.02
GND3 on L2: 41.78,5.61 41.77,6.01 41.71,6.75 42.09,7.24 41.53,8.59 40.18,9.14 3.05,9.14 1.34,9.85 0.64,11.56 0.64,73.15 1.34,74.86 3.05,75.56 123.95,75.56 125.66,74.86 126.36,73.15 126.36,11.56 125.66,9.85 123.95,9.14 77.01,9.14 75.79,8.57 75.46,7.27 75.4,5.62 75.41,5.61 54.78,5.61 54.75,5.64 54.7,7.16 54.75,8.17 53.69,8.9 52.46,8.49 52.44,7.24 52.41,5.76 52.44,5.61 52.44,5.61
GND3 on L3: 41.78,5.61 41.77,6.01 41.71,6.75 42.09,7.24 41.53,8.59 40.18,9.14 3.05,9.14 1.34,9.85 0.64,11.56 0.64,73.15 1.34,74.86 3.05,75.56 123.95,75.56 125.66,74.86 126.36,73.15 126.36,11.56 125.66,9.85 123.95,9.14 77.01,9.14 75.79,8.57 75.46,7.27 75.4,5.62 75.41,5.61 54.78,5.61 54.75,5.64 54.7,7.16 54.75,8.17 53.69,8.9 52.46,8.49 52.44,7.24 52.41,5.76 52.44,5.61

Small or netless copper shapes (teardrops, artwork), in the pictures only: 6 on TOP, 26 on BOTTOM, 3 on L2, 1 on L3

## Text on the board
BOTTOM: 4
Ref Des/Silkscreen Bottom: BOARD:Tx0p | AIC:Tx0n | BOARD:Tx1n | AIC:Tx0p | BOARD:Tx1p | BOARD:Tx2n | BOARD:Tx2p | BOARD:Tx0n | AIC:Tx1n | AIC:Tx1p | BOARD:Rx0n | BOARD:Rx1p | BOARD:Rx1n | BOARD:Rx0p | AIC:Tx2n | AIC:Tx2p | 1.800 | 3.600 | 3.716 | 4.080 | 5.589 | AIC:Rx0n | FACE TO FACE | LOAD | SHORT | Fmin 1.240 Fmax 5.150 | Fmin .300 Fmax 1.240 | AIC:Rx0p | PRIMARY THRU | SECONDARY 1 | AIC:Rx1n | Fmin 5.150 Fmax 20 | SECONDARY 2 | SECONDARY 3 | AIC:Rx1p
User.Comments: 35 | 15
Ref Des/Silkscreen Top: PCIe Gen 4.0 Surface Mount Connector Characterization | 1.800 | 3.600 | 3.716 | 4.080 | 5.589 | AIC:Rx0n | Add-in Card Rev 1.0 | FACE TO FACE | Fmin 1.240 Fmax 5.150 | LOAD | Fmin .300 Fmax 1.240 | Baseboard Rev 1.0 | SHORT | Fmin 5.150 Fmax 20 | PRIMARY THRU | SECONDARY 1 | SECONDARY 2 | SECONDARY 3 | AIC:Rx1n | AIC:Rx1p | AIC:Tx0p | PCIe Gen 4.0 Thru-Hole Connector Characterization | AIC:Tx0n | AIC:Tx1n | AIC:Tx1p | AIC:Tx2p | AIC:Tx2n | AIC:Rx0p | SMT BOARD | THERMAL | RELIEF GND | THRU HOLE | BOARD
DIMENSION: -A- | -B- | 4 PLACES | 16 PLACES | .500 | 4 | 11 | 5 | SEE DETAIL B page 2 | 9 | SEE DETAIL A 8 places | Suggested panel usage with 7" off axis rotation. | artwork sheet 13 OF 13 | FOR REFERENCE ONLY
User.10: -A- | -B- | 9 | 12
User.17: * | 1 | 01
User.19: .331 MIN | 8.40 MIN | 12.15 | .478 | .055 | 1.40 | .394 | 10 | .059 | 22.15 | 1.5 | .872 | .787 | 20 | .037 | 0.95 | .075+/-.002 | 1.9+/-.06 | .039 | 1 | 8.51 | .335 | .020 x 45 TYP | 0.5 | FULL RADIUS 1X | 2116 | (PLATED 1/2oz Cu) | (GND 1 oz Cu) | LAYER 1 | LAYER 2 | LAYER 3 | LAYER 4 | (GND 1oz Cu) | (MEGTRON 6) | CORE | OVERALL BOARD THICKNESS SPECIFICATION | TOTAL- | ADJUST CORE THICKNESS TO ACHIEVE | THICKNESS | .0021  MIN ,0014 | .0047  MAX ,0048 | .0014  +/- .0002 | .0047  MAX .0048 | .0021 MIN .0014 | .062 +.006 -.006 | TOLERANCE | 2of2 | .062+.006-.006 | [1.30] | .051 | ACROSS PADS | +/- .010 | 11  MARK PANEL NUMBER IN APPROXIMATE AREA SHOWN. AVOID SILKSCREEN  OVER ANY TRACES | 12  REMOVE ALL NON-FUNCTIONAL VIA PADS. | 13  SURFACE FINISH: ENIG | 10. CONTROLLED IMPEDANCE 42.5 OHMS +/- 5% 10.2 MIL TRACE LAYERS 1 & 4 | 9 GOLD FINGERS PER DETAIL A. PLATE MINIMUM 20 MICRO-INCHES GOLD OVER | NOTES: UNLESS OTHERWISE SPECIFIED: | 1. PART NUMBER IS PARENT ITEM IDENTIFICATION NUMBER ON | 2. THIS DRAWING ALSO EXISTS ON ELECTRONIC MEDIA. | 4  THE CENTER OF THESE TWO HOLES ESTABLISH DATUM -A-. | 5  DATUM -B- IS ESTABLISHED PERPENDICULAR TO DATUM -A- THROUGH | 6. DIMENSIONING AND TOLERANCING PER ASME Y14.5 | 7  FAB VENDOR MAY ADD COPPER THIEVING AS NEEDED ON OUTER LAYERS | 8  THESE HOLES TO BE EPOXY FILLED AND PLATED OVER. | 3  VENDOR TO USE BLUE SOLDERMASK UNDER WHITE INK | MINIMUM 150 MICRO-INCHES OF NICKEL. | CONTROLLED IMPEDANCE 50 OHMS +/- 5% 7.8 MIL TRACE LAYERS 1 & 4 | ENGINEERING BILL OF MATERIAL. | THE CENTER OF THIS HOLE. | COPPER THIEVING NO CLOSER THAN O.100" TO ANY COPPER FEATURE OR LAYER WINDOW. | W | SCALE: NONE | 70 +/-3 | 4 LAYER STACKUP | LAYER STACKING | 9 | DETAIL-B | VIEW B-B
User.20: PB,DOC,PCIE GEN4 CONN TEST BOARD
User.21: 12
User.41: 2 places | 8 PLACES | DO NOT SCALE | CENTER POINT OF PERF TAB DIMENSIONED ON MAIN DRAWING | DRILL DATA IN DRILL FILE FOR ALL PERF TAB DRILLS. | - | 1:1 | 1 of 2 | B | 8 | PB,FAB,PCIE GEN4 CONN TEST BOARD | PRIMARY SIDE VIEW | DETAIL A | XXXXXX | XX
User.42: FIGURE | SIZE | 10.0 | 28.0 | 29.5 | 25.0 | 63.0 | 93.0 | 156.0 | 250.0 | DRILL CHART: TOP to BOTTOM | ALL UNITS ARE IN MILS | TOLERANCE | +0.0/-10.0 | +4.0/-8.0 | +3.0/-3.0 | PLATED | NON-PLATED | QTY | 256 | 656 | 1 | 63 | 64 | 128 | 2 | 18 | 12
